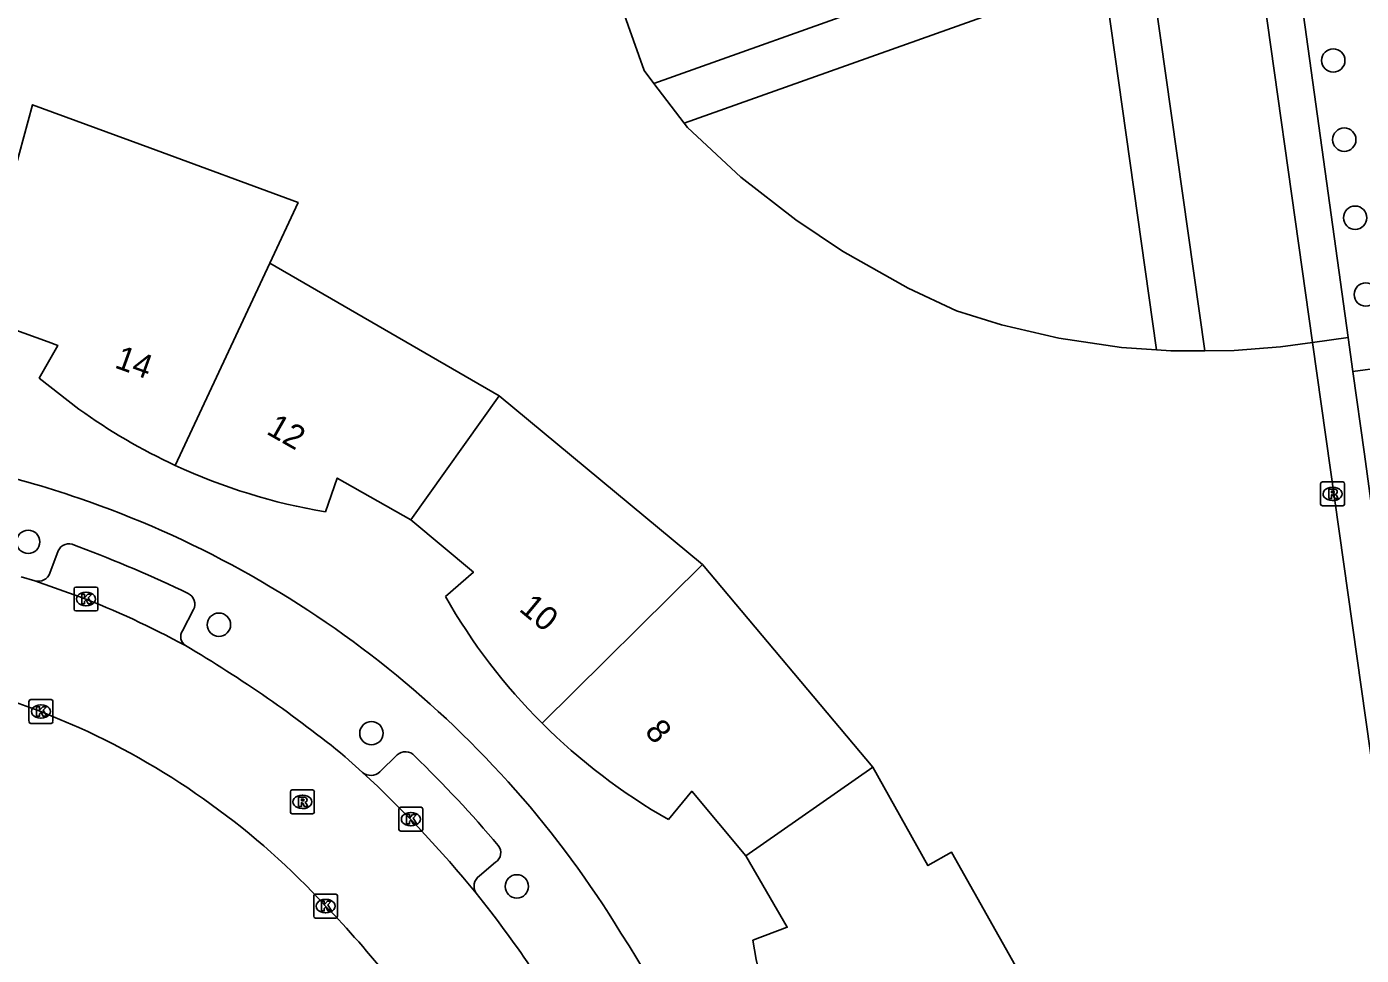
# Model space of a CAD drawing. Extents: x 159053 to 160041, y 380450 to 381422.
# Drawn here: x 159497.8 to 159553.7, y 380865 to 380903.9 of the extents above; entities that cross this region are included whole.
import ezdxf

# ---------------------------------------------------------------- set-up
doc = ezdxf.new("R2010")
doc.units = 0
for name, color, linetype in [('IMGEO_Boom', 7, 'Continuous'), ('IMGEO_Groenvoorziening', 7, 'Continuous'), ('IMGEO_Kolk', 7, 'Continuous'), ('IMGEO_Pand', 7, 'Continuous'), ('IMGEO_Pand_nummerreeks', 7, 'Continuous'), ('IMGEO_Rijbaan_lokaal_open', 7, 'Continuous'), ('IMGEO_Rioolput', 7, 'Continuous'), ('IMGEO_Voetpad_open', 7, 'Continuous')]:
    doc.layers.add(name, color=color, linetype=linetype)

msp = doc.modelspace()

# ---------------------------------------------------------------- linework, layer by layer
at = {"layer": 'IMGEO_Boom'}
for centre in [(159552.53, 380902.484), (159552.992, 380899.166), (159553.446, 380895.897), (159553.894, 380892.678), (159497.875, 380882.316), (159505.861, 380878.844), (159512.248, 380874.299), (159518.338, 380867.883)]:
    msp.add_circle(centre, 0.489, dxfattribs=at)
at = {"layer": 'IMGEO_Groenvoorziening'}
for points in [[(159547.152, 380890.326), (159544.826, 380906.798), (159544.155, 380908.682), (159524.073, 380901.524)], [(159545.127, 380890.36), (159542.903, 380906.113), (159525.341, 380899.853)], [(159524.073, 380901.524), (159523.668, 380902.058), (159522.547, 380905.226)], [(159525.341, 380899.853), (159524.073, 380901.524)], [(159545.127, 380890.36), (159543.655, 380890.464), (159541.042, 380890.85), (159538.641, 380891.409), (159536.753, 380891.994), (159534.72, 380892.946), (159531.982, 380894.488), (159530.018, 380895.803), (159527.717, 380897.601), (159525.48, 380899.67), (159525.341, 380899.853)], [(159551.664, 380890.669), (159550.324, 380890.488), (159548.378, 380890.332), (159547.152, 380890.326)], [(159547.152, 380890.326), (159545.722, 380890.318), (159545.127, 380890.36)]]:
    msp.add_lwpolyline(points, dxfattribs=at)
at = {"layer": 'IMGEO_Kolk'}
for p, q in [((159499.794, 380879.496), (159499.794, 380880.348)), ((159499.869, 380880.422), (159500.721, 380880.422)), ((159500.282, 380880.202), (159500.307, 380880.202)), ((159500.795, 380880.348), (159500.795, 380879.496)), ((159500.721, 380879.422), (159499.869, 380879.422)), ((159500.305, 380879.642), (159500.28, 380879.642)), ((159497.907, 380874.783), (159497.907, 380875.635)), ((159497.982, 380875.709), (159498.834, 380875.709)), ((159498.395, 380875.489), (159498.42, 380875.489)), ((159498.908, 380875.635), (159498.908, 380874.783)), ((159498.418, 380874.929), (159498.393, 380874.929)), ((159498.834, 380874.709), (159497.982, 380874.709)), ((159513.401, 380870.272), (159513.401, 380871.124)), ((159513.476, 380871.198), (159514.328, 380871.198)), ((159514.402, 380871.124), (159514.402, 380870.272)), ((159513.889, 380870.978), (159513.914, 380870.978)), ((159514.328, 380870.198), (159513.476, 380870.198)), ((159513.912, 380870.418), (159513.887, 380870.418)), ((159509.831, 380866.631), (159509.831, 380867.483)), ((159509.906, 380867.557), (159510.758, 380867.557)), ((159510.319, 380867.337), (159510.344, 380867.337)), ((159510.832, 380867.483), (159510.832, 380866.631)), ((159510.758, 380866.557), (159509.906, 380866.557)), ((159510.342, 380866.777), (159510.317, 380866.777))]:
    msp.add_line(p, q, dxfattribs=at)
for points in [[(159499.794, 380879.496), (159499.794, 380880.348)], [(159499.869, 380880.422), (159500.721, 380880.422)], [(159500.115, 380880.122), (159500.238, 380880.122), (159500.238, 380879.971), (159500.368, 380880.122), (159500.532, 380880.122), (159500.386, 380879.971), (159500.539, 380879.722), (159500.387, 380879.722), (159500.302, 380879.886), (159500.238, 380879.819), (159500.238, 380879.722), (159500.115, 380879.722), (159500.115, 380880.122)], [(159500.795, 380880.348), (159500.795, 380879.496)], [(159500.721, 380879.422), (159499.869, 380879.422)], [(159497.907, 380874.783), (159497.907, 380875.635)], [(159497.982, 380875.709), (159498.834, 380875.709)], [(159498.908, 380875.635), (159498.908, 380874.783)], [(159498.228, 380875.409), (159498.351, 380875.409), (159498.351, 380875.258), (159498.481, 380875.409), (159498.645, 380875.409), (159498.499, 380875.258), (159498.652, 380875.009), (159498.5, 380875.009), (159498.415, 380875.173), (159498.351, 380875.106), (159498.351, 380875.009), (159498.228, 380875.009), (159498.228, 380875.409)], [(159498.834, 380874.709), (159497.982, 380874.709)], [(159513.401, 380870.272), (159513.401, 380871.124)], [(159513.476, 380871.198), (159514.328, 380871.198)], [(159514.402, 380871.124), (159514.402, 380870.272)], [(159513.722, 380870.898), (159513.845, 380870.898), (159513.845, 380870.747), (159513.975, 380870.898), (159514.139, 380870.898), (159513.993, 380870.747), (159514.146, 380870.498), (159513.994, 380870.498), (159513.909, 380870.662), (159513.845, 380870.595), (159513.845, 380870.498), (159513.722, 380870.498), (159513.722, 380870.898)], [(159514.328, 380870.198), (159513.476, 380870.198)], [(159509.831, 380866.631), (159509.831, 380867.483)], [(159509.906, 380867.557), (159510.758, 380867.557)], [(159510.152, 380867.257), (159510.275, 380867.257), (159510.275, 380867.106), (159510.405, 380867.257), (159510.569, 380867.257), (159510.423, 380867.106), (159510.576, 380866.857), (159510.424, 380866.857), (159510.339, 380867.021), (159510.275, 380866.954), (159510.275, 380866.857), (159510.152, 380866.857), (159510.152, 380867.257)], [(159510.832, 380867.483), (159510.832, 380866.631)], [(159510.758, 380866.557), (159509.906, 380866.557)]]:
    msp.add_lwpolyline(points, dxfattribs=at)
for centre, start, end in [((159499.871, 380880.346), 91.552, 178.448), ((159499.871, 380880.346), 91.552, 178.448), ((159500.719, 380880.346), 1.552, 88.448), ((159500.719, 380880.346), 1.552, 88.448), ((159499.871, 380879.498), 181.552, 268.448), ((159499.871, 380879.498), 181.552, 268.448), ((159500.719, 380879.498), 271.552, 358.448), ((159500.719, 380879.498), 271.552, 358.448), ((159497.984, 380875.633), 91.552, 178.448), ((159497.984, 380875.633), 91.552, 178.448), ((159498.832, 380875.633), 1.552, 88.448), ((159498.832, 380875.633), 1.552, 88.448), ((159497.984, 380874.785), 181.552, 268.448), ((159497.984, 380874.785), 181.552, 268.448), ((159498.832, 380874.785), 271.552, 358.448), ((159498.832, 380874.785), 271.552, 358.448), ((159513.478, 380871.122), 91.552, 178.448), ((159513.478, 380871.122), 91.552, 178.448), ((159514.326, 380871.122), 1.552, 88.448), ((159514.326, 380871.122), 1.552, 88.448), ((159513.478, 380870.274), 181.552, 268.448), ((159513.478, 380870.274), 181.552, 268.448), ((159514.326, 380870.274), 271.552, 358.448), ((159514.326, 380870.274), 271.552, 358.448), ((159509.908, 380867.481), 91.552, 178.448), ((159509.908, 380867.481), 91.552, 178.448), ((159510.756, 380867.481), 1.552, 88.448), ((159510.756, 380867.481), 1.552, 88.448), ((159509.908, 380866.633), 181.552, 268.448), ((159509.908, 380866.633), 181.552, 268.448), ((159510.756, 380866.633), 271.552, 358.448), ((159510.756, 380866.633), 271.552, 358.448)]:
    msp.add_arc(centre, 0.0765, start, end, dxfattribs=at)
for centre, major_axis, ratio, start_param, end_param in [((159500.281, 380879.922), (-0.387, 0.002), 0.722429, 4.712389, 7.853982), ((159500.306, 380879.922), (-0.39, 0.002), 0.717154, 1.570796, 4.712389), ((159498.394, 380875.209), (-0.387, 0.002), 0.722429, 4.712389, 7.853982), ((159498.419, 380875.209), (-0.39, 0.002), 0.717154, 1.570796, 4.712389), ((159513.888, 380870.698), (-0.387, 0.002), 0.722429, 4.712389, 7.853982), ((159513.913, 380870.698), (-0.39, 0.002), 0.717154, 1.570796, 4.712389), ((159510.318, 380867.057), (-0.387, 0.002), 0.722429, 4.712389, 7.853982), ((159510.343, 380867.057), (-0.39, 0.002), 0.717154, 1.570796, 4.712389)]:
    msp.add_ellipse(centre, major_axis=major_axis, ratio=ratio, start_param=start_param, end_param=end_param, dxfattribs=at)
at = {"layer": 'IMGEO_Pand'}
for points in [[(159508, 380893.993), (159509.178, 380896.53), (159502.961, 380898.82), (159498.048, 380900.63), (159497.327, 380897.94), (159495.677, 380891.788), (159498.705, 380890.693), (159499.11, 380890.546), (159498.336, 380889.178), (159500, 380887.872)], [(159508, 380893.993), (159504.035, 380885.518)], [(159517.592, 380888.432), (159508, 380893.993)], [(159555.83, 380889.792), (159553.356, 380889.448)], [(159553.356, 380889.448), (159553.837, 380885.99), (159554.18, 380883.516)], [(159517.592, 380888.432), (159513.892, 380883.235)], [(159526.109, 380881.368), (159517.592, 380888.432)], [(159510.323, 380883.572), (159510.816, 380884.987), (159513.892, 380883.235)], [(159513.892, 380883.235), (159516.522, 380881.044), (159515.347, 380880.028)], [(159519.394, 380874.718), (159526.109, 380881.368)], [(159533.241, 380872.87), (159526.109, 380881.368)], [(159533.241, 380872.87), (159527.931, 380869.165)], [(159538.674, 380863.21), (159538.483, 380863.549), (159539.471, 380864.105), (159536.542, 380869.313), (159535.554, 380868.757), (159533.241, 380872.87)], [(159524.686, 380870.684), (159525.661, 380871.869), (159527.931, 380869.165)], [(159527.931, 380869.165), (159529.662, 380866.173), (159528.217, 380865.632)]]:
    msp.add_lwpolyline(points, dxfattribs=at)
for centre, radius, start, end in [((159514.386, 380907.895), 24.655, 234.3048, 245.177), ((159514.43, 380907.975), 24.746, 245.1611, 260.4466), ((159537.029, 380892.355), 24.941, 209.621, 225.0044), ((159537.046, 380892.386), 24.975, 225.0268, 240.338), ((159552.669, 380869.696), 24.787, 189.4357, 204.7914)]:
    msp.add_arc(centre, radius, start, end, dxfattribs=at)
at = {"layer": 'IMGEO_Rijbaan_lokaal_open'}
for points in [[(159497.584, 380880.855), (159498.154, 380880.684)], [(159500, 380880.029), (159498.154, 380880.684)], [(159496.247, 380875.965), (159497.175, 380875.659), (159498.404, 380875.21), (159500, 380874.538)], [(159511.153, 380873.313), (159511.881, 380872.656)], [(159516.632, 380867.595), (159517.247, 380866.821)]]:
    msp.add_lwpolyline(points, dxfattribs=at)
for centre, radius, start, end in [((159486.561, 380845.059), 37.463, 61.4626, 68.9774), ((159477.445, 380832.005), 53.316, 50.7853, 59.5587), ((159486.779, 380845.41), 31.988, 42.5905, 65.5873), ((159479.235, 380837.249), 48.16, 39.0576, 47.3232), ((159480.923, 380838.553), 40.954, 38.3899, 44.1086), ((159477.57, 380836.473), 49.953, 28.7692, 37.4119)]:
    msp.add_arc(centre, radius, start, end, dxfattribs=at)
at = {"layer": 'IMGEO_Rioolput'}
for p, q in [((159552.001, 380883.9), (159552.001, 380884.752)), ((159552.076, 380884.826), (159552.928, 380884.826)), ((159552.489, 380884.606), (159552.514, 380884.606)), ((159553.002, 380884.752), (159553.002, 380883.9)), ((159552.512, 380884.046), (159552.487, 380884.046)), ((159552.928, 380883.826), (159552.076, 380883.826)), ((159508.856, 380870.996), (159508.856, 380871.848)), ((159508.931, 380871.922), (159509.783, 380871.922)), ((159509.344, 380871.702), (159509.369, 380871.702)), ((159509.857, 380871.848), (159509.857, 380870.996)), ((159509.367, 380871.142), (159509.342, 380871.142)), ((159509.783, 380870.922), (159508.931, 380870.922))]:
    msp.add_line(p, q, dxfattribs=at)
for points in [[(159552.001, 380883.9), (159552.001, 380884.752)], [(159552.076, 380884.826), (159552.928, 380884.826)], [(159552.59, 380884.524), (159552.338, 380884.526), (159552.338, 380884.126)], [(159552.516, 380884.445), (159552.462, 380884.445), (159552.462, 380884.364)], [(159553.002, 380884.752), (159553.002, 380883.9)], [(159552.338, 380884.126), (159552.462, 380884.126), (159552.462, 380884.288), (159552.473, 380884.288)], [(159552.462, 380884.364), (159552.514, 380884.364)], [(159552.52, 380884.259), (159552.591, 380884.126), (159552.731, 380884.126), (159552.666, 380884.252)], [(159552.928, 380883.826), (159552.076, 380883.826)], [(159508.856, 380870.996), (159508.856, 380871.848)], [(159508.931, 380871.922), (159509.783, 380871.922)], [(159509.445, 380871.62), (159509.193, 380871.622), (159509.193, 380871.222)], [(159509.857, 380871.848), (159509.857, 380870.996)], [(159509.193, 380871.222), (159509.317, 380871.222), (159509.317, 380871.384), (159509.328, 380871.384)], [(159509.371, 380871.541), (159509.317, 380871.541), (159509.317, 380871.46)], [(159509.317, 380871.46), (159509.369, 380871.46)], [(159509.375, 380871.355), (159509.446, 380871.222), (159509.586, 380871.222), (159509.521, 380871.348)], [(159509.783, 380870.922), (159508.931, 380870.922)]]:
    msp.add_lwpolyline(points, dxfattribs=at)
for centre, radius, start, end in [((159552.078, 380884.75), 0.0765, 91.552, 178.448), ((159552.078, 380884.75), 0.0765, 91.552, 178.448), ((159552.522, 380884.349), 0.0964, 77.0061, 93.1865), ((159552.536, 380884.406), 0.0378, 276.6634, 79.6772), ((159552.589, 380884.414), 0.109, 350.3612, 89.416), ((159552.926, 380884.75), 0.0765, 1.552, 88.448), ((159552.926, 380884.75), 0.0765, 1.552, 88.448), ((159552.078, 380883.902), 0.0765, 181.552, 268.448), ((159552.078, 380883.902), 0.0765, 181.552, 268.448), ((159552.472, 380884.235), 0.0533, 26.0293, 88.6989), ((159552.498, 380884.553), 0.19, 274.7715, 282.9687), ((159552.587, 380884.414), 0.112, 277.5842, 350.9817), ((159552.571, 380884.199), 0.108, 29.5134, 73.7905), ((159552.926, 380883.902), 0.0765, 271.552, 358.448), ((159552.926, 380883.902), 0.0765, 271.552, 358.448), ((159508.933, 380871.846), 0.0765, 91.552, 178.448), ((159508.933, 380871.846), 0.0765, 91.552, 178.448), ((159509.444, 380871.51), 0.109, 350.3612, 89.416), ((159509.781, 380871.846), 0.0765, 1.552, 88.448), ((159509.781, 380871.846), 0.0765, 1.552, 88.448), ((159509.327, 380871.331), 0.0533, 26.0293, 88.6989), ((159509.353, 380871.649), 0.19, 274.7715, 282.9687), ((159509.377, 380871.445), 0.0964, 77.0061, 93.1865), ((159509.391, 380871.502), 0.0378, 276.6634, 79.6772), ((159509.442, 380871.51), 0.112, 277.5842, 350.9817), ((159509.426, 380871.295), 0.108, 29.5134, 73.7905), ((159508.933, 380870.998), 0.0765, 181.552, 268.448), ((159508.933, 380870.998), 0.0765, 181.552, 268.448), ((159509.781, 380870.998), 0.0765, 271.552, 358.448), ((159509.781, 380870.998), 0.0765, 271.552, 358.448)]:
    msp.add_arc(centre, radius, start, end, dxfattribs=at)
for centre, major_axis, ratio, start_param, end_param in [((159552.488, 380884.326), (-0.387, 0.002), 0.722429, 4.712389, 7.853982), ((159552.513, 380884.326), (-0.39, 0.002), 0.717154, 1.570796, 4.712389), ((159509.343, 380871.422), (-0.387, 0.002), 0.722429, 4.712389, 7.853982), ((159509.368, 380871.422), (-0.39, 0.002), 0.717154, 1.570796, 4.712389)]:
    msp.add_ellipse(centre, major_axis=major_axis, ratio=ratio, start_param=start_param, end_param=end_param, dxfattribs=at)
at = {"layer": 'IMGEO_Voetpad_open'}
for points in [[(159548.504, 380913.051), (159549.185, 380908.224), (159551.664, 380890.669)], [(159553.159, 380890.871), (159550.053, 380913.261)], [(159551.664, 380890.669), (159553.159, 380890.871)], [(159551.664, 380890.669), (159558.918, 380839.284)], [(159553.356, 380889.448), (159553.159, 380890.871)], [(159498.783, 380881.002), (159499.133, 380881.938)], [(159499.808, 380882.178), (159500, 380882.106)], [(159504.797, 380879.481), (159504.334, 380878.594)], [(159512.602, 380872.676), (159513.327, 380873.396)], [(159517.45, 380868.893), (159516.769, 380868.33)]]:
    msp.add_lwpolyline(points, dxfattribs=at)
for centre, radius, start, end in [((159486.052, 380843.443), 43.026, 71.0836, 77.0537), ((159486.084, 380843.565), 42.9, 31.404, 71.071), ((159499.578, 380881.756), 0.481, 61.3818, 157.7645), ((159480.384, 380829.843), 55.823, 64.324, 69.4272), ((159498.297, 380881.183), 0.519, 254.0587, 339.5803), ((159504.356, 380879.707), 0.496, 332.8201, 64.305), ((159504.722, 380878.347), 0.46, 147.5502, 234.9635), ((159513.665, 380873.014), 0.511, 40.9225, 131.4914), ((159479.039, 380837.088), 50.404, 40.1625, 46.0029), ((159512.23, 380873.084), 0.552, 230.8098, 312.3681), ((159517.184, 380869.295), 0.482, 303.534, 38.8637), ((159517.099, 380867.888), 0.552, 126.7947, 212.0884), ((159479.625, 380837.852), 51.411, 10.905, 33.0883)]:
    msp.add_arc(centre, radius, start, end, dxfattribs=at)

# ---------------------------------------------------------------- texts
at = {"layer": 'IMGEO_Pand_nummerreeks'}
for s, rotation, p in [('14', 340.1126, (159501.448, 380889.63)), ('12', 330.4541, (159507.804, 380886.865)), ('10', 320.2008, (159518.389, 380879.453)), ('8', 310.0733, (159523.657, 380874.355))]:
    msp.add_text(s, height=1, rotation=rotation, dxfattribs=at).set_placement(p)

doc.saveas('drawing.dxf')
